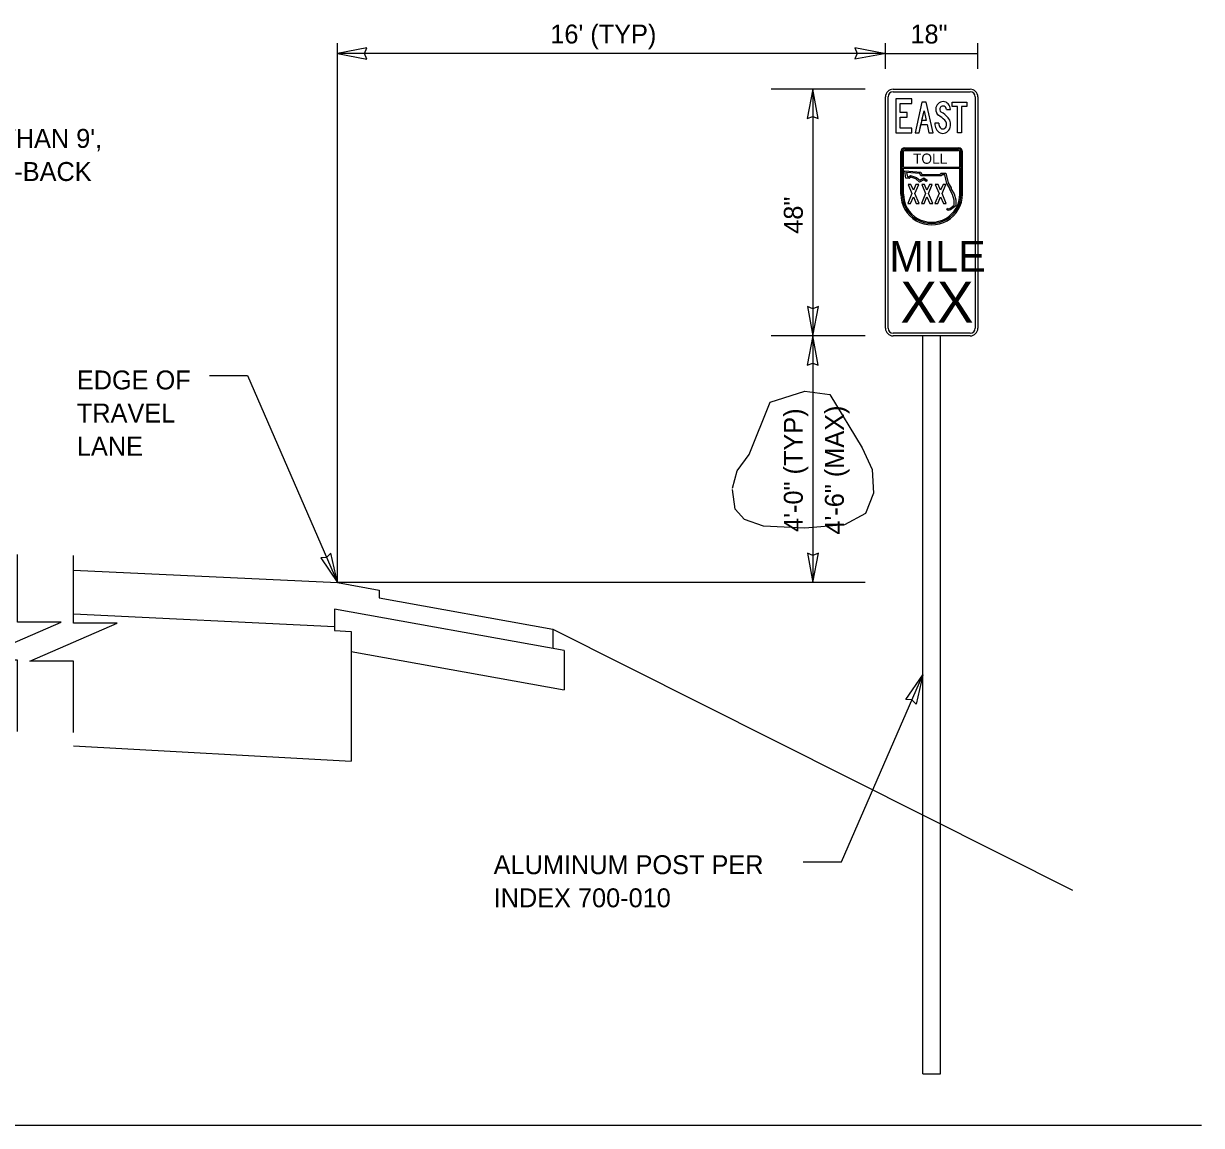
# Model space of a CAD drawing. Extents: x 57428 to 58066, y 11696 to 12105.
# Drawn here: x 57891.5 to 58065.9, y 11934.3 to 12097.3 of the extents above; entities that cross this region are included whole.
import ezdxf

# ---------------------------------------------------------------- set-up
doc = ezdxf.new("R2010")
doc.units = 0
for name, color, linetype in [('52', 7, 'Continuous'), ('62', 7, 'Continuous'), ('Default', 7, 'Continuous'), ('DimLines_dp', 7, 'Continuous'), ('NonPlottingEle_dp', 7, 'Continuous'), ('SignPanel', 7, 'Continuous'), ('TextMisc', 7, 'Continuous'), ('XSGrdLine_ex', 7, 'Continuous')]:
    doc.layers.add(name, color=color, linetype=linetype)

msp = doc.modelspace()

# ---------------------------------------------------------------- linework, layer by layer
at = {"layer": '52'}
msp.add_line((58016.11, 12014.58), (57937.99, 12014.58), dxfattribs=at)
at = {"layer": '62'}
msp.add_lwpolyline([(57996.45, 12028.52), (57997.15, 12031.12), (57998.95, 12033.52), (58002.06, 12041.28), (58007.16, 12042.88), (58010.86, 12042.38), (58015.66, 12034.52), (58017.16, 12031.32), (58017.36, 12027.82), (58016.16, 12024.81), (58013.06, 12023.11), (58007.16, 12022.61), (58001.05, 12022.91), (57998.25, 12023.91), (57996.85, 12025.41), (57996.45, 12028.32)], dxfattribs=at)
at = {"layer": 'Default'}
for points in [[(57890.6, 11992.52), (57890.6, 12003.08), (57884.14, 12003.08), (57890.6, 12005.89), (57897.06, 12008.71), (57890.6, 12008.71), (57890.6, 12018.71)], [(57898.9, 11992.39), (57898.9, 12002.95), (57892.44, 12002.95), (57898.9, 12005.76), (57905.36, 12008.57), (57898.9, 12008.57), (57898.9, 12018.57)]]:
    msp.add_lwpolyline(points, dxfattribs=at)
at = {"layer": 'DimLines_dp'}
for p, q in [((57937.99, 12014.58), (57937.99, 12094.4)), ((57942.34, 12093.67), (57937.99, 12092.86)), ((58019.11, 12092.86), (57937.99, 12092.86)), ((57937.99, 12092.86), (57942.34, 12092.02)), ((57942.01, 12092.86), (57942.34, 12093.67)), ((57942.34, 12092.02), (57942.01, 12092.86)), ((58018.92, 12092.86), (58014.57, 12093.7)), ((58014.57, 12093.7), (58014.9, 12092.86)), ((58014.9, 12092.86), (58014.57, 12092.05)), ((58014.57, 12092.05), (58018.92, 12092.86)), ((58019.11, 12090.57), (58019.11, 12094.4)), ((58019.11, 12092.86), (58032.79, 12092.86)), ((58032.79, 12090.57), (58032.79, 12094.4)), ((58016.11, 12087.57), (58002.18, 12087.57)), ((58008.36, 12087.57), (58007.52, 12083.22)), ((58008.36, 12087.57), (58008.36, 12051.07)), ((58009.17, 12083.22), (58008.36, 12087.57)), ((58007.52, 12083.22), (58008.36, 12083.55)), ((58008.36, 12083.55), (58009.17, 12083.22)), ((58008.36, 12055.09), (58007.55, 12055.42)), ((58007.55, 12055.42), (58008.36, 12051.07)), ((58008.36, 12055.09), (58007.55, 12055.42)), ((58007.55, 12055.42), (58008.36, 12051.07)), ((58008.36, 12051.07), (58009.2, 12055.42)), ((58009.2, 12055.42), (58008.36, 12055.09)), ((58008.36, 12051.07), (58009.2, 12055.42)), ((58009.2, 12055.42), (58008.36, 12055.09)), ((58016.11, 12051.07), (58002.18, 12051.07)), ((58008.36, 12051.07), (58007.52, 12046.72)), ((58008.36, 12051.07), (58008.36, 12014.58)), ((58009.17, 12046.72), (58008.36, 12051.07)), ((58007.52, 12046.72), (58008.36, 12047.05)), ((58008.36, 12047.05), (58009.17, 12046.72)), ((57919.02, 12045.19), (57924.67, 12045.19)), ((57924.67, 12045.19), (57937.99, 12014.57)), ((57936.38, 12018.26), (57935.51, 12018.24)), ((57935.51, 12018.24), (57937.99, 12014.57)), ((57937.02, 12018.9), (57936.38, 12018.26)), ((57937.99, 12014.57), (57937.02, 12018.9)), ((58008.36, 12018.6), (58007.55, 12018.93)), ((58007.55, 12018.93), (58008.36, 12014.58)), ((58008.36, 12014.58), (58009.2, 12018.93)), ((58009.2, 12018.93), (58008.36, 12018.6)), ((58012.58, 11973.24), (58024.62, 12000.91)), ((58022.14, 11997.25), (58024.62, 12000.91)), ((58024.62, 12000.91), (58023.65, 11996.59)), ((58023.01, 11997.23), (58022.14, 11997.25)), ((58023.65, 11996.59), (58023.01, 11997.23)), ((58006.93, 11973.24), (58012.58, 11973.24))]:
    msp.add_line(p, q, dxfattribs=at)
at = {"layer": 'NonPlottingEle_dp'}
for p, q in [((58024.62, 11980.19), (58024.62, 12051.07)), ((58027.28, 11978.86), (58027.28, 12051.07)), ((58024.62, 11941.87), (58024.62, 11980.19)), ((58027.28, 11941.87), (58027.28, 11978.86)), ((58024.62, 11941.87), (58027.28, 11941.87))]:
    msp.add_line(p, q, dxfattribs=at)
at = {"layer": 'SignPanel'}
for p, q in [((58028.14, 12084.57), (58028.73, 12084.57)), ((58028.14, 12084.57), (58028.73, 12084.57)), ((58028.14, 12084.57), (58028.73, 12084.57)), ((58027.01, 12082.53), (58026.41, 12082.53)), ((58027.01, 12082.53), (58026.41, 12082.53)), ((58027.01, 12082.53), (58026.41, 12082.53)), ((58021.96, 12078.91), (58029.94, 12078.91)), ((58021.39, 12072.06), (58021.39, 12078.34)), ((58021.58, 12072.06), (58021.58, 12078.34)), ((58021.77, 12076.05), (58021.77, 12078.34)), ((58021.96, 12078.71), (58029.94, 12078.71)), ((58021.96, 12078.52), (58029.94, 12078.52)), ((58030.13, 12076.05), (58030.13, 12078.34)), ((58030.32, 12072.06), (58030.32, 12078.34)), ((58030.51, 12072.06), (58030.51, 12078.34)), ((58021.77, 12076.05), (58030.13, 12076.05)), ((58021.77, 12072.06), (58021.77, 12075.86)), ((58021.77, 12075.86), (58030.13, 12075.86)), ((58022.15, 12074.41), (58021.98, 12075.5)), ((58021.98, 12075.5), (58024.36, 12075.31)), ((58024.36, 12075.31), (58024.5, 12074.97)), ((58030.13, 12072.06), (58030.13, 12075.86)), ((58022.61, 12074.35), (58022.15, 12074.41)), ((58024.2, 12075.09), (58022.25, 12075.24)), ((58022.25, 12075.24), (58022.35, 12074.61)), ((58022.35, 12074.61), (58022.54, 12074.59)), ((58022.54, 12074.59), (58022.81, 12074.8)), ((58022.86, 12074.55), (58022.61, 12074.35)), ((58022.81, 12074.8), (58023.73, 12074.5)), ((58023.61, 12074.3), (58022.86, 12074.55)), ((58023.24, 12075.16), (58023.24, 12075.16)), ((58024.15, 12073.8), (58023.61, 12074.3)), ((58023.73, 12074.5), (58024.18, 12074.09)), ((58024.78, 12074.17), (58024.15, 12073.8)), ((58024.18, 12074.09), (58024.79, 12074.45)), ((58024.34, 12074.74), (58024.2, 12075.09)), ((58027.35, 12074.74), (58024.34, 12074.74)), ((58024.5, 12074.97), (58027.23, 12074.97)), ((58025.16, 12073.92), (58024.78, 12074.17)), ((58024.79, 12074.45), (58025.29, 12074.11)), ((58025.29, 12074.11), (58025.16, 12073.92)), ((58027.23, 12074.97), (58027.33, 12075.12)), ((58027.33, 12075.12), (58028.06, 12075.12)), ((58027.45, 12074.89), (58027.35, 12074.74)), ((58027.88, 12074.89), (58027.45, 12074.89)), ((58028.18, 12073.6), (58027.88, 12074.89)), ((58028.06, 12075.12), (58028.4, 12073.69)), ((58028.62, 12072.9), (58028.18, 12073.6)), ((58028.4, 12073.69), (58028.85, 12072.96)), ((58028.62, 12072.72), (58028.62, 12072.9)), ((58029.05, 12072.01), (58028.62, 12072.72)), ((58028.85, 12072.96), (58028.85, 12072.78)), ((58028.85, 12072.78), (58029.26, 12072.11)), ((58029.28, 12071.15), (58029.05, 12072.01)), ((58029.26, 12072.11), (58029.51, 12071.18)), ((58028.65, 12069.92), (58029.28, 12070.43)), ((58029.51, 12070.32), (58028.76, 12069.7)), ((58029.28, 12070.43), (58029.28, 12071.15)), ((58029.51, 12071.18), (58029.51, 12070.32)), ((58028.18, 12069.78), (58028.31, 12069.96)), ((58028.4, 12069.62), (58028.18, 12069.78)), ((58028.31, 12069.96), (58028.45, 12069.87)), ((58028.76, 12069.7), (58028.4, 12069.62)), ((58028.45, 12069.87), (58028.65, 12069.92))]:
    msp.add_line(p, q, dxfattribs=at)
for points in [[(58020.25, 12087.57), (58031.65, 12087.57)], [(58019.11, 12052.21), (58019.11, 12086.43)], [(58019.49, 12052.21), (58019.49, 12086.43)], [(58020.25, 12087.19), (58031.65, 12087.19)], [(58032.41, 12086.43), (58032.41, 12052.21)], [(58032.79, 12086.43), (58032.79, 12052.21)], [(58031.65, 12051.45), (58020.25, 12051.45)], [(58031.65, 12051.07), (58020.25, 12051.07)]]:
    msp.add_lwpolyline(points, dxfattribs=at)
for points in [[(58021.31, 12081.8), (58021.31, 12083.42), (58022.33, 12083.42), (58022.33, 12084.13), (58021.31, 12084.13), (58021.31, 12085.45), (58023.03, 12085.45), (58023.03, 12086.15), (58020.66, 12086.15), (58020.66, 12081.09), (58023.03, 12081.09), (58023.03, 12081.8)], [(58021.31, 12081.8), (58021.31, 12083.42), (58022.33, 12083.42), (58022.33, 12084.13), (58021.31, 12084.13), (58021.31, 12085.45), (58023.03, 12085.45), (58023.03, 12086.15), (58020.66, 12086.15), (58020.66, 12081.09), (58023.03, 12081.09), (58023.03, 12081.8)], [(58021.31, 12081.8), (58021.31, 12083.42), (58022.33, 12083.42), (58022.33, 12084.13), (58021.31, 12084.13), (58021.31, 12085.45), (58023.03, 12085.45), (58023.03, 12086.15), (58020.66, 12086.15), (58020.66, 12081.09), (58023.03, 12081.09), (58023.03, 12081.8)], [(58025.28, 12082.32), (58025.55, 12081.09), (58026.16, 12081.09), (58025.14, 12085.67), (58024.51, 12085.67), (58023.49, 12081.09), (58024.09, 12081.09), (58024.37, 12082.32)], [(58024.51, 12082.96), (58024.37, 12082.32), (58025.28, 12082.32), (58025.55, 12081.09), (58026.16, 12081.09), (58025.14, 12085.67), (58024.51, 12085.67), (58023.49, 12081.09), (58024.09, 12081.09), (58024.82, 12084.36), (58025.14, 12082.96)], [(58024.51, 12082.96), (58024.37, 12082.32), (58025.28, 12082.32), (58025.55, 12081.09), (58026.16, 12081.09), (58025.14, 12085.67), (58024.51, 12085.67), (58023.49, 12081.09), (58024.09, 12081.09), (58024.82, 12084.36), (58025.14, 12082.96)], [(58024.82, 12084.36), (58025.14, 12082.96), (58024.51, 12082.96)], [(58029.79, 12085.03), (58029.01, 12085.03), (58029.01, 12085.67), (58031.16, 12085.67), (58031.16, 12085.03), (58030.38, 12085.03), (58030.38, 12081.09), (58029.79, 12081.09)], [(58029.79, 12085.03), (58029.01, 12085.03), (58029.01, 12085.67), (58031.16, 12085.67), (58031.16, 12085.03), (58030.38, 12085.03), (58030.38, 12081.09), (58029.79, 12081.09)], [(58029.79, 12085.03), (58029.01, 12085.03), (58029.01, 12085.67), (58031.16, 12085.67), (58031.16, 12085.03), (58030.38, 12085.03), (58030.38, 12081.09), (58029.79, 12081.09)], [(58022.84, 12070.64), (58023.25, 12071.62), (58023.66, 12070.64), (58024.08, 12070.64), (58023.46, 12072.13), (58024.03, 12073.49), (58023.61, 12073.49), (58023.25, 12072.64), (58022.89, 12073.49), (58022.46, 12073.49), (58023.03, 12072.13), (58022.41, 12070.64)], [(58024.86, 12070.64), (58025.26, 12071.62), (58025.67, 12070.64), (58026.1, 12070.64), (58025.48, 12072.13), (58026.05, 12073.49), (58025.62, 12073.49), (58025.26, 12072.64), (58024.91, 12073.49), (58024.48, 12073.49), (58025.05, 12072.13), (58024.43, 12070.64)], [(58026.87, 12070.64), (58027.28, 12071.62), (58027.69, 12070.64), (58028.12, 12070.64), (58027.49, 12072.13), (58028.07, 12073.49), (58027.64, 12073.49), (58027.28, 12072.64), (58026.92, 12073.49), (58026.49, 12073.49), (58027.07, 12072.13), (58026.44, 12070.64)]]:
    msp.add_lwpolyline(points, close=True, dxfattribs=at)
for centre, radius, start, end in [((58020.25, 12086.43), 1.14, 90, 180), ((58031.65, 12086.43), 1.14, 0, 90), ((58020.25, 12086.43), 0.76, 90, 180), ((58031.65, 12086.43), 0.76, 0, 90), ((58020.25, 12052.21), 1.14, 180, 270), ((58020.25, 12052.21), 0.76, 180, 270), ((58031.65, 12052.21), 1.14, 270, 360), ((58031.65, 12052.21), 0.76, 270, 360)]:
    msp.add_arc(centre, radius, start, end, dxfattribs=at)
for centre, major_axis, ratio, start_param, end_param in [((58027.64, 12084.54), (0, 1.19), 0.91923, 4.736267, 7.790596), ((58027.64, 12084.54), (0, 1.19), 0.91923, 4.736267, 7.790596), ((58027.64, 12084.54), (0, 1.19), 0.91923, 4.736267, 7.790596), ((58027.53, 12084.57), (0, 1.07), 0.91923, 1.534831, 2.511766), ((58027.53, 12084.57), (0, 1.07), 0.91923, 1.534831, 2.511766), ((58027.53, 12084.57), (0, 1.07), 0.91923, 1.534831, 2.511766), ((58027.57, 12084.59), (0, 0.46), 0.91923, 0.87378, 2.656959), ((58027.57, 12084.59), (0, 0.46), 0.91923, 0.87378, 2.656959), ((58027.57, 12084.59), (0, 0.46), 0.91923, 0.87378, 2.656959), ((58027.63, 12084.52), (0, 0.558), 0.91923, 4.786904, 7.140738), ((58027.63, 12084.52), (0, 0.558), 0.91923, 4.786904, 7.140738), ((58027.63, 12084.52), (0, 0.558), 0.91923, 4.786904, 7.140738), ((58025.43, 12080.34), (0, 4.39), 0.91923, 5.462886, 5.782242), ((58025.43, 12080.34), (0, 4.39), 0.91923, 5.462886, 5.782242), ((58025.43, 12080.34), (0, 4.39), 0.91923, 5.462886, 5.782242), ((58027.79, 12082.46), (0, 1.5), 0.91923, 1.526364, 2.701682), ((58027.79, 12082.46), (0, 1.5), 0.91923, 1.526364, 2.701682), ((58027.79, 12082.46), (0, 1.5), 0.91923, 1.526364, 2.701682), ((58024.92, 12079.64), (0, 4.63), 0.91923, 5.515137, 5.786988), ((58024.92, 12079.64), (0, 4.63), 0.91923, 5.515137, 5.786988), ((58024.92, 12079.64), (0, 4.63), 0.91923, 5.515137, 5.786988), ((58027.84, 12082.48), (0, 0.911), 0.91923, 1.524757, 2.28214), ((58027.84, 12082.48), (0, 0.911), 0.91923, 1.524757, 2.28214), ((58027.84, 12082.48), (0, 0.911), 0.91923, 1.524757, 2.28214), ((58027.44, 12082.34), (0, 0.792), 0.91923, 4.254409, 5.632398), ((58027.44, 12082.34), (0, 0.792), 0.91923, 4.254409, 5.632398), ((58027.44, 12082.34), (0, 0.792), 0.91923, 4.254409, 5.632398), ((58027.45, 12082.34), (0, 1.42), 0.91923, 4.260987, 5.485755), ((58027.45, 12082.34), (0, 1.42), 0.91923, 4.260987, 5.485755), ((58027.45, 12082.34), (0, 1.42), 0.91923, 4.260987, 5.485755), ((58027.6, 12082.27), (0, 1.24), 0.91923, 2.786047, 4.251692), ((58027.6, 12082.27), (0, 1.24), 0.91923, 2.786047, 4.251692), ((58027.6, 12082.27), (0, 1.24), 0.91923, 2.786047, 4.251692), ((58027.62, 12082.26), (0, 0.581), 0.91923, 2.261787, 4.23006), ((58027.62, 12082.26), (0, 0.581), 0.91923, 2.261787, 4.23006), ((58027.62, 12082.26), (0, 0.581), 0.91923, 2.261787, 4.23006), ((58021.96, 12078.33), (0, 0.57), 0.9997, 0, 1.570796), ((58029.94, 12078.33), (0, 0.57), 0.9997, 4.712389, 6.283185), ((58021.96, 12078.33), (0, 0.38), 0.9997, 0, 1.570796), ((58021.96, 12078.33), (0, 0.19), 0.9997, 0, 1.570796), ((58029.94, 12078.33), (0, 0.38), 0.9997, 4.712389, 6.283185), ((58029.94, 12078.33), (0, 0.19), 0.9997, 4.712389, 6.283185), ((58025.95, 12072.06), (0, -4.56), 0.9997, 4.712389, 7.853982), ((58025.95, 12072.06), (0, -4.37), 0.9997, 4.712389, 7.853982), ((58025.95, 12072.06), (0, -4.18), 0.9997, 4.712389, 7.853982)]:
    msp.add_ellipse(centre, major_axis=major_axis, ratio=ratio, start_param=start_param, end_param=end_param, dxfattribs=at)
at = {"layer": 'TextMisc'}
msp.add_line((58065.89, 11934.25), (57709.55, 11934.25), dxfattribs=at)
at = {"layer": 'XSGrdLine_ex'}
for p, q in [((57937.99, 12014.57), (57944.15, 12013.46)), ((57944.15, 12013.46), (57944.15, 12012.29)), ((57944.15, 12012.29), (57969.87, 12007.66)), ((57937.57, 12010.63), (57937.57, 12007.48)), ((57971.57, 12004.51), (57937.57, 12010.63)), ((57937.57, 12007.48), (57940.04, 12007.33)), ((57940.04, 12007.33), (57940.04, 11988.15)), ((57969.87, 12007.66), (57969.87, 12004.82)), ((57940.04, 12004.37), (57971.57, 11998.7)), ((57971.57, 12004.51), (57971.57, 11998.7)), ((57898.9, 11990.43), (57940.04, 11988.15))]:
    msp.add_line(p, q, dxfattribs=at)
for points in [[(57898.9, 12016.43), (57937.99, 12014.57)], [(57898.9, 12009.93), (57937.57, 12008.09)], [(57969.87, 12007.66), (58046.82, 11969.06)]]:
    msp.add_lwpolyline(points, dxfattribs=at)

# ---------------------------------------------------------------- texts
at = {"layer": 'DimLines_dp'}
for s, p in [("16' (TYP)", (57969.5, 12094.33)), ('18"', (58022.81, 12094.33)), ("FOR DISTANCES LESS THAN 9',", (57846.05, 12078.89)), ('MOUNT SIGNS BACK-TO-BACK', (57846.05, 12073.99)), ('EDGE OF ', (57899.41, 12043.15)), ('TRAVEL ', (57899.41, 12038.25)), ('LANE', (57899.41, 12033.35)), ('ALUMINUM POST PER', (57961.11, 11971.43)), ('INDEX 700-010', (57961.11, 11966.53))]:
    msp.add_text(s, height=2.8, dxfattribs=at).set_placement(p)
for s, p in [('48"', (58006.87, 12066.18)), ('4\'-6" (MAX)', (58012.95, 12021.67)), ('4\'-0" (TYP)', (58006.87, 12022.07))]:
    msp.add_text(s, height=2.8, rotation=90, dxfattribs=at).set_placement(p)
at = {"layer": 'SignPanel'}
for s, height, p in [('TOLL', 1.519, (58023.19, 12076.53)), ('MILE', 4.562, (58019.7, 12060.57)), ('XX', 6.083, (58021.31, 12053.01))]:
    msp.add_text(s, height=height, dxfattribs=at).set_placement(p)

doc.saveas('drawing.dxf')
